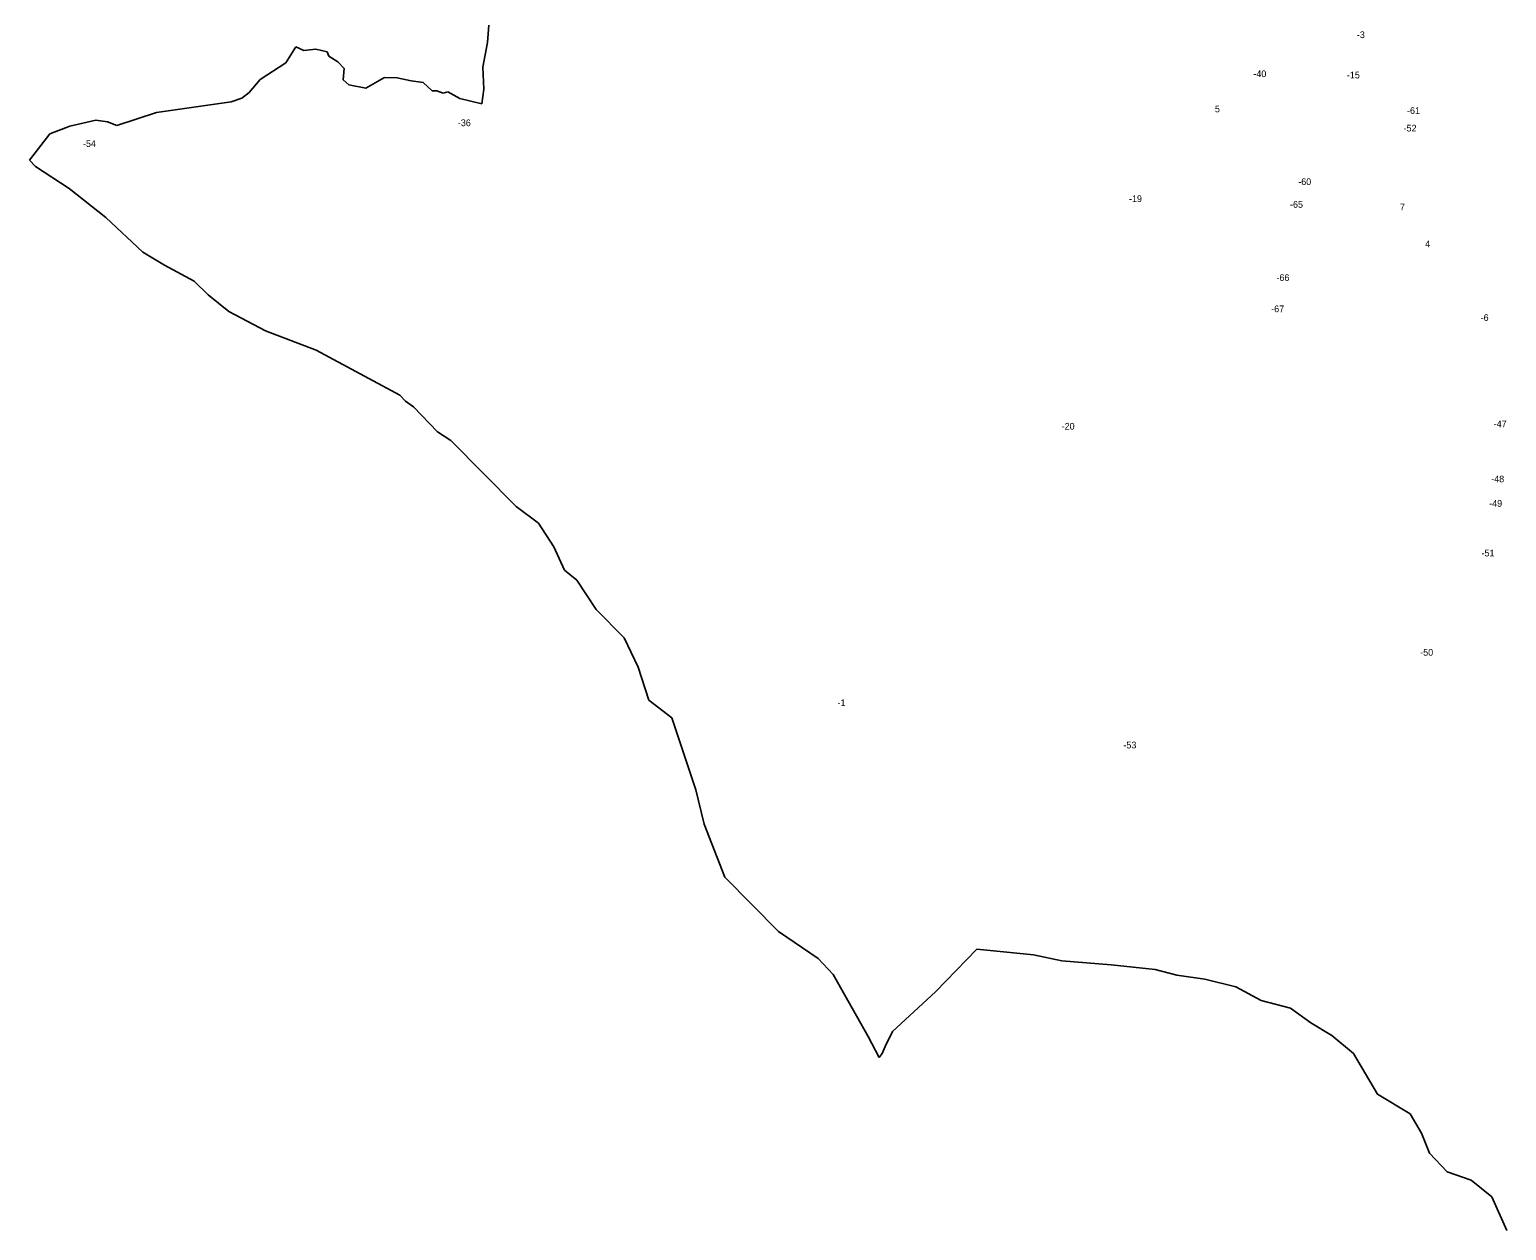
# Model space of a CAD drawing. Extents: x -790002 to -785628, y -971900 to -967971.
# Drawn here: x -790002 to -787802, y -971569 to -969779 of the extents above; entities that cross this region are included whole.
import ezdxf

# ---------------------------------------------------------------- set-up
doc = ezdxf.new("R2010")
doc.units = 0
doc.layers.add('Vrstva 13', color=7, linetype='Continuous')
doc.layers.add('Vrstva 15', color=7, linetype='Continuous')

msp = doc.modelspace()

# ---------------------------------------------------------------- linework, layer by layer
at = {"layer": 'Vrstva 13'}
for p, q in [((-789319.79, -969799), (-789317.88, -969773.12)), ((-789620.28, -969829.01), (-789605.32, -969805.14)), ((-789605.32, -969805.14), (-789593.58, -969810.65)), ((-789593.58, -969810.65), (-789575.62, -969808.81)), ((-789575.62, -969808.81), (-789558.61, -969812.48)), ((-789558.61, -969812.48), (-789556.06, -969818.95)), ((-789556.06, -969818.95), (-789542.88, -969827.74)), ((-789326.97, -969835.74), (-789319.79, -969799)), ((-789658.6, -969853.93), (-789620.28, -969829.01)), ((-789542.88, -969827.74), (-789533.3, -969837.32)), ((-789533.3, -969837.32), (-789535.02, -969854.57)), ((-789325.22, -969868.33), (-789326.97, -969835.74)), ((-789674.89, -969873.26), (-789658.6, -969853.93)), ((-789535.02, -969854.57), (-789526.4, -969862.08)), ((-789526.4, -969862.08), (-789500.97, -969866.65)), ((-789500.97, -969866.65), (-789473.1, -969850.75)), ((-789473.1, -969850.75), (-789454.43, -969851.39)), ((-789454.43, -969851.39), (-789433.51, -969855.94)), ((-789433.51, -969855.94), (-789415.79, -969858.26)), ((-789415.79, -969858.26), (-789402.37, -969870.8)), ((-789701.87, -969887.31), (-789685.91, -969881.72)), ((-789685.91, -969881.72), (-789674.89, -969873.26)), ((-789402.37, -969870.8), (-789395.15, -969871.04)), ((-789395.15, -969871.04), (-789386.05, -969874.24)), ((-789386.05, -969874.24), (-789378.87, -969872.16)), ((-789378.87, -969872.16), (-789361.14, -969882.22)), ((-789361.14, -969882.22), (-789328.09, -969890.05)), ((-789328.09, -969890.05), (-789325.22, -969868.33)), ((-789872.25, -969922.45), (-789812.85, -969903.12)), ((-789812.85, -969903.12), (-789701.87, -969887.31)), ((-789971.72, -969935.06), (-789941.87, -969923.41)), ((-789941.87, -969923.41), (-789903.23, -969914.78)), ((-789903.23, -969914.78), (-789886.15, -969917.02)), ((-789886.15, -969917.02), (-789872.25, -969922.45)), ((-790002.06, -969974.04), (-789971.72, -969935.06)), ((-789993.28, -969983.62), (-790002.06, -969974.04)), ((-789942.81, -970016.37), (-789993.28, -969983.62)), ((-789888.45, -970059.82), (-789942.81, -970016.37)), ((-789833.52, -970111.25), (-789888.45, -970059.82)), ((-789800.95, -970130.74), (-789833.52, -970111.25)), ((-789756.87, -970154.38), (-789800.95, -970130.74)), ((-789735.8, -970174.83), (-789756.87, -970154.38)), ((-789705.14, -970199.75), (-789735.8, -970174.83)), ((-789650.53, -970228.5), (-789705.14, -970199.75)), ((-789574.85, -970257.57), (-789650.53, -970228.5)), ((-789450.55, -970324.5), (-789574.85, -970257.57)), ((-789441.77, -970333.29), (-789450.55, -970324.5)), ((-789430.11, -970341.6), (-789441.77, -970333.29)), ((-789394.34, -970379.29), (-789430.11, -970341.6)), ((-789374.23, -970391.92), (-789394.34, -970379.29)), ((-789277.31, -970490.32), (-789374.23, -970391.92)), ((-789243.78, -970515.07), (-789277.31, -970490.32)), ((-789220.95, -970550.53), (-789243.78, -970515.07)), ((-789205.3, -970585.51), (-789220.95, -970550.53)), ((-789186.77, -970600.2), (-789205.3, -970585.51)), ((-789157.95, -970643.81), (-789186.77, -970600.2)), ((-789116.12, -970685.98), (-789157.95, -970643.81)), ((-789095.36, -970729.74), (-789116.12, -970685.98)), ((-789079.56, -970779.26), (-789095.36, -970729.74)), ((-789045.07, -970805.45), (-789079.56, -970779.26)), ((-789009.38, -970912.47), (-789045.07, -970805.45)), ((-788996.94, -970963.76), (-789009.38, -970912.47)), ((-788966.07, -971042.66), (-788996.94, -970963.76)), ((-788886.17, -971123.62), (-788966.07, -971042.66)), ((-788827.02, -971164.1), (-788886.17, -971123.62)), ((-788590.7, -971150.09), (-788652.45, -971213.66)), ((-788506.13, -971158.65), (-788590.7, -971150.09)), ((-788464.37, -971167.48), (-788506.13, -971158.65)), ((-788804.97, -971187.98), (-788827.02, -971164.1)), ((-788390.69, -971173.7), (-788464.37, -971167.48)), ((-788325.32, -971180.71), (-788390.69, -971173.7)), ((-788292.63, -971188.75), (-788325.32, -971180.71)), ((-788752.57, -971280.37), (-788804.97, -971187.98)), ((-788250.87, -971194.98), (-788292.63, -971188.75)), ((-788204.69, -971206.4), (-788250.87, -971194.98)), ((-788652.45, -971213.66), (-788716.26, -971272.83)), ((-788167.07, -971226.9), (-788204.69, -971206.4)), ((-788123.5, -971238.06), (-788167.07, -971226.9)), ((-788093.41, -971260.12), (-788123.5, -971238.06)), ((-788061.76, -971278.81), (-788093.41, -971260.12)), ((-788736.24, -971311.76), (-788752.57, -971280.37)), ((-788716.26, -971272.83), (-788727.42, -971295.15)), ((-788029.59, -971305.54), (-788061.76, -971278.81)), ((-788731.57, -971305.79), (-788736.24, -971311.76)), ((-788727.42, -971295.15), (-788731.57, -971305.79)), ((-787993.8, -971366.52), (-788029.59, -971305.54)), ((-787945.29, -971395.84), (-787993.8, -971366.52)), ((-787928.43, -971424.65), (-787945.29, -971395.84)), ((-787916.5, -971454.24), (-787928.43, -971424.65)), ((-787890.3, -971482), (-787916.5, -971454.24)), ((-787854.24, -971494.71), (-787890.3, -971482)), ((-787823.63, -971519.37), (-787854.24, -971494.71)), ((-787801.06, -971569.46), (-787823.63, -971519.37))]:
    msp.add_line(p, q, dxfattribs=at)

# ---------------------------------------------------------------- texts
at = {"layer": 'Vrstva 15'}
for s, p in [('-3', (-788024.64, -969792.28)), ('-40', (-788178.806, -969850.35)), ('-15', (-788039.484, -969852.35)), ('5', (-788236.096, -969902.78)), ('-61', (-787949.908, -969905.22)), ('-36', (-789363.964, -969923.49)), ('-52', (-787955.03, -969931.44)), ('-54', (-789922.456, -969954.43)), ('-60', (-788111.914, -970011.3)), ('-19', (-788364.098, -970036.61)), ('-65', (-788124.184, -970045.17)), ('7', (-787960.446, -970048.98)), ('4', (-787922.822, -970103.92)), ('-66', (-788144.347, -970154.25)), ('-67', (-788152.232, -970200.76)), ('-6', (-787840.224, -970213.81)), ('-20', (-788464.4, -970375.79)), ('-47', (-787820.714, -970372.23)), ('-48', (-787824.486, -970454.37)), ('-49', (-787827.51, -970490.82)), ('-51', (-787838.934, -970564.8)), ('-50', (-787930.25, -970712.77)), ('-1', (-788798.244, -970787.78)), ('-53', (-788372.4, -970850.95))]:
    msp.add_text(s, height=10, dxfattribs=at).set_placement(p)

doc.saveas('drawing.dxf')
